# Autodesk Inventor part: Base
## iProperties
Shininess: 77.0
Length Units: 11269
Angle Units: 11279
Time Units: 11290
Mass Units: 11283
Length Display Precision: 3
Angle Display Precision: 2
Created: 2002-02
Part Number: Base
Document SubType Name: Modeling
Designer: ***
Density: 0.0
Volumn: 0.0
Area: 0.0
PropertySet Name: Model Information
Control State: 0
Master: False
Checked Out: False
Author: ***
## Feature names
1. Extrusion1
2. Extrusion2
3. Extrusion3
4. Hole1
5. Mirror1
6. Extrusion4
7. Extrusion5
